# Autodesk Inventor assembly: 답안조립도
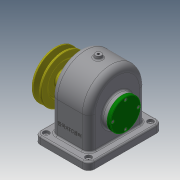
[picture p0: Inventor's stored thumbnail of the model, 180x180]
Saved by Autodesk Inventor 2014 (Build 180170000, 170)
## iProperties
Created: 2016-10
Part Number: 답안조립도
Document SubType Name: Assembly
Designer: 703-17
Author: 703-17
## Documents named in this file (15)
- C:\Users\703-17\Desktop\461008V1002\답안조립도.iam
- C:\Users\703-17\Desktop\461008V1002\본체.ipt
- C:\Users\703-17\Desktop\461008V1002\V-벨트풀리.ipt
- C:\Users\703-17\Desktop\461008V1002\뒤커버.ipt
- C:\Users\703-17\Desktop\461008V1002\멈춤나사 - M4x10.ipt
- C:\Users\703-17\Desktop\461008V1002\베어링 6203.ipt
- C:\Users\703-17\Desktop\461008V1002\볼트 M3 x 8.ipt
- C:\Users\703-17\Desktop\461008V1002\볼트 M3 x 10.ipt
- C:\Users\703-17\Desktop\461008V1002\부시.ipt
- C:\Users\703-17\Desktop\461008V1002\스퍼기어.ipt
- C:\Users\703-17\Desktop\461008V1002\앞커버.ipt
- C:\Users\703-17\Desktop\461008V1002\오일씰 28 40 8.ipt
- C:\Users\703-17\Desktop\461008V1002\축.ipt
- C:\Users\703-17\Desktop\461008V1002\키 - 5 x 5 x 18.ipt
- C:\Users\703-17\Desktop\461008V1002\키 - 6 x 6 x 22.ipt
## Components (9 placed, 3 different names)
1. V-벨트풀리:1 — 각도:5
2. ISO 4762 M3 x 8:1
3. ISO 4762 M3 x 8:2
4. ISO 4762 M3 x 8:3
5. ISO 4762 M3 x 8:4
6. ISO 4762 M3 x 10:1
7. ISO 4762 M3 x 10:2
8. ISO 4762 M3 x 10:3
9. ISO 4762 M3 x 10:4
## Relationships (1: Angle 1)
- 각도:5 [Angle]: V-벨트풀리:1
